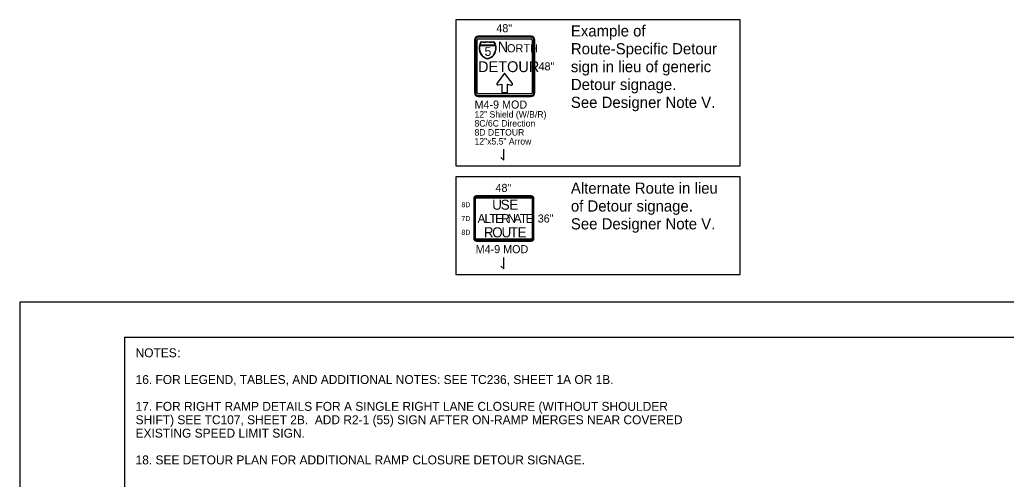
# Model space of a CAD drawing. Extents: x 99999 to 100116, y 99995 to 100013.
# Drawn here: x 100059.06 to 100067.9, y 100009.1 to 100013.22 of the extents above; entities that cross this region are included whole.
import ezdxf

# ---------------------------------------------------------------- set-up
doc = ezdxf.new("R2010")
doc.units = 0
for name, color, linetype in [('SH_GI_GeneralNotesBodyText', 7, 'Continuous'), ('SH_GI_PlotLimits', 7, 'Continuous'), ('SH_GI_SheetBorder', 7, 'Continuous'), ('TR_SN_ConstructionSigns', 7, 'Continuous'), ('TR_WZ_WorkZoneDetails', 7, 'Continuous')]:
    doc.layers.add(name, color=color, linetype=linetype)

msp = doc.modelspace()

# ---------------------------------------------------------------- linework, layer by layer
at = {"layer": 'SH_GI_PlotLimits'}
msp.add_lwpolyline([(100059.0625, 99999.6875), (100076.0625, 99999.6875), (100076.0625, 100010.6875), (100059.0625, 100010.6875)], close=True, dxfattribs=at)
at = {"layer": 'SH_GI_SheetBorder'}
for q in [(100060, 100000), (100075.75, 100010.375)]:
    msp.add_line((100060, 100010.375), q, dxfattribs=at)
at = {"layer": 'TR_SN_ConstructionSigns'}
for p, q in [((100063.1354, 100013.0373), (100063.1354, 100012.5648)), ((100063.1438, 100013.0373), (100063.1438, 100012.5648)), ((100063.1579, 100012.5648), (100063.1579, 100013.0373)), ((100063.6416, 100013.0711), (100063.1691, 100013.0711)), ((100063.6416, 100013.0626), (100063.1691, 100013.0626)), ((100063.1691, 100013.0486), (100063.6416, 100013.0486)), ((100063.6529, 100013.0373), (100063.6529, 100012.5648)), ((100063.6669, 100012.5648), (100063.6669, 100013.0373)), ((100063.6754, 100012.5648), (100063.6754, 100013.0373)), ((100063.3228, 100012.9875), (100063.1823, 100012.9875)), ((100063.1823, 100012.9875), (100063.3228, 100012.9875)), ((100063.1834, 100012.9912), (100063.3217, 100012.9912)), ((100063.3217, 100012.9912), (100063.1834, 100012.9912)), ((100063.6416, 100012.5536), (100063.1691, 100012.5536)), ((100063.1691, 100012.5395), (100063.6416, 100012.5395)), ((100063.1691, 100012.5311), (100063.6416, 100012.5311)), ((100063.6424, 100011.6405), (100063.153, 100011.6405)), ((100063.6424, 100011.6335), (100063.153, 100011.6335)), ((100063.153, 100011.6236), (100063.6424, 100011.6236)), ((100063.1277, 100011.6152), (100063.1277, 100011.2608)), ((100063.1347, 100011.6152), (100063.1347, 100011.2608)), ((100063.1446, 100011.2608), (100063.1446, 100011.6152)), ((100063.6508, 100011.6152), (100063.6508, 100011.2608)), ((100063.6607, 100011.2608), (100063.6607, 100011.6152)), ((100063.6677, 100011.2608), (100063.6677, 100011.6152)), ((100063.6424, 100011.2524), (100063.153, 100011.2524)), ((100063.153, 100011.2425), (100063.6424, 100011.2425)), ((100063.153, 100011.2355), (100063.6424, 100011.2355))]:
    msp.add_line(p, q, dxfattribs=at)
msp.add_lwpolyline([(100063.3367, 100012.6494), (100063.3356, 100012.6478), (100063.335, 100012.6461), (100063.3347, 100012.6441), (100063.3348, 100012.6424), (100063.335, 100012.6412), (100063.3356, 100012.6398), (100063.3373, 100012.6375), (100063.3386, 100012.6364), (100063.34, 100012.6355), (100063.3417, 100012.6348), (100063.3432, 100012.6345), (100063.3447, 100012.6343), (100063.3465, 100012.6343), (100063.3478, 100012.6346), (100063.3795, 100012.6424), (100063.3795, 100012.5671), (100063.4307, 100012.5671), (100063.4307, 100012.6429), (100063.4617, 100012.6337), (100063.4647, 100012.6331), (100063.4681, 100012.6334), (100063.4703, 100012.6342), (100063.4733, 100012.6362), (100063.4752, 100012.6389), (100063.476, 100012.6414), (100063.4761, 100012.6436), (100063.4754, 100012.6463), (100063.4746, 100012.6477), (100063.4051, 100012.7405), (100063.3367, 100012.6494)], dxfattribs=at)
for centre, radius, start, end in [((100063.1691, 100013.0373), 0.0337, 90, 180), ((100063.1691, 100013.0373), 0.0253, 90, 180), ((100063.1691, 100013.0373), 0.0113, 90, 180), ((100063.6416, 100013.0373), 0.0338, 360, 90), ((100063.6416, 100013.0373), 0.0253, 360, 90), ((100063.6416, 100013.0373), 0.0113, 360, 90), ((100063.2725, 100012.9642), 0.0973, 142.16169, 258.18105), ((100063.2715, 100012.9633), 0.0925, 164.85517, 258.18105), ((100063.2715, 100012.9633), 0.0925, 164.85517, 258.18105), ((100063.2715, 100012.9633), 0.0925, 142.16169, 162.48397), ((100063.2715, 100012.9633), 0.0925, 142.16169, 162.48397), ((100063.2245, 100013.1212), 0.1014, 253.48525, 286.04538), ((100063.2259, 100013.1124), 0.0964, 253.48525, 286.04538), ((100063.2259, 100013.1124), 0.0964, 253.48525, 286.04538), ((100063.2806, 100013.1212), 0.1014, 253.95462, 286.51475), ((100063.2792, 100013.1124), 0.0964, 253.95462, 286.51475), ((100063.2792, 100013.1124), 0.0964, 253.95462, 286.51475), ((100063.2325, 100012.9642), 0.0974, 281.90384, 37.84925), ((100063.2335, 100012.9633), 0.0925, 281.90384, 15.1558), ((100063.2335, 100012.9633), 0.0925, 281.90384, 15.1558), ((100063.2335, 100012.9633), 0.0925, 17.52691, 37.84925), ((100063.2335, 100012.9633), 0.0925, 17.52691, 37.84925), ((100063.1691, 100012.5648), 0.0338, 180, 270), ((100063.1691, 100012.5648), 0.0253, 180, 270), ((100063.1691, 100012.5648), 0.0113, 180, 270), ((100063.6416, 100012.5648), 0.0337, 270, 360), ((100063.6416, 100012.5648), 0.0253, 270, 0), ((100063.6416, 100012.5648), 0.0113, 270, 0), ((100063.153, 100011.6152), 0.0253, 90, 180), ((100063.153, 100011.6152), 0.0183, 90, 180), ((100063.153, 100011.6152), 0.00844, 90, 180), ((100063.6424, 100011.6152), 0.0253, 360, 90), ((100063.6424, 100011.6152), 0.0183, 360, 90), ((100063.6424, 100011.6152), 0.00844, 360, 90), ((100063.153, 100011.2608), 0.0253, 180, 270), ((100063.153, 100011.2608), 0.0183, 180, 270), ((100063.153, 100011.2608), 0.00844, 180, 270), ((100063.6424, 100011.2608), 0.0253, 270, 360), ((100063.6424, 100011.2608), 0.0183, 270, 0), ((100063.6424, 100011.2608), 0.00844, 270, 0)]:
    msp.add_arc(centre, radius, start, end, dxfattribs=at)
at = {"layer": 'TR_WZ_WorkZoneDetails'}
for p, q in [((100063.3963, 100011.9605), (100063.3963, 100012.0605)), ((100063.3713, 100011.9855), (100063.3963, 100011.9605)), ((100063.3963, 100010.9875), (100063.3963, 100011.0875)), ((100063.3713, 100011.0125), (100063.3963, 100010.9875))]:
    msp.add_line(p, q, dxfattribs=at)
for points in [[(100062.9666, 100011.9105), (100065.5143, 100011.9105), (100065.5143, 100013.2191), (100062.9666, 100013.2191)], [(100062.9666, 100010.9375), (100065.5143, 100010.9375), (100065.5143, 100011.8105), (100062.9666, 100011.8105)]]:
    msp.add_lwpolyline(points, close=True, dxfattribs=at)

# ---------------------------------------------------------------- texts
at = {"layer": 'SH_GI_GeneralNotesBodyText'}
for s, p in [('NOTES', (100060.1, 100010.195)), (':', (100060.4743, 100010.195)), ('16. FOR LEGEND, TABLES, AND ADDITIONAL NOTES: SEE TC236, SHEET 1A OR 1B.', (100060.1, 100009.955)), ('17. FOR RIGHT RAMP DETAILS FOR A SINGLE RIGHT LANE CLOSURE (WITHOUT SHOULDER ', (100060.1, 100009.715)), ('SHIFT) SEE TC107, SHEET 2B.  ADD R2-1 (55) SIGN AFTER ON-RAMP MERGES NEAR COVERED ', (100060.1, 100009.595)), ('EXISTING SPEED LIMIT SIGN.', (100060.1, 100009.475)), ('18. SEE DETOUR PLAN FOR ADDITIONAL RAMP CLOSURE DETOUR SIGNAGE.', (100060.1, 100009.235))]:
    msp.add_text(s, height=0.08, rotation=360, dxfattribs=at).set_placement(p)
at = {"layer": 'TR_SN_ConstructionSigns'}
for s, height, p in [('48"', 0.072, (100063.3306, 100013.1071)), ('5', 0.081, (100063.2253, 100012.8951)), ('N', 0.0972, (100063.3432, 100012.9267)), ('ORTH', 0.0729, (100063.4264, 100012.9267)), ('DETOUR', 0.0972, (100063.1668, 100012.7497)), ('48"', 0.072, (100063.7086, 100012.7651)), ('M4-9 MOD', 0.072, (100063.1354, 100012.4231)), ('12" Shield (W/B/R)', 0.0576, (100063.1354, 100012.3424)), ('8C/6C Direction', 0.0576, (100063.1354, 100012.2618)), ('8D DETOUR', 0.0576, (100063.1354, 100012.1811)), ('12"x5.5" Arrow', 0.0576, (100063.1354, 100012.1005)), ('48"', 0.072, (100063.323, 100011.6765)), ('36"', 0.072, (100063.7015, 100011.402)), ('M4-9 MOD', 0.072, (100063.1457, 100011.1275))]:
    msp.add_text(s, height=height, rotation=360, dxfattribs=at).set_placement(p)
for s, height, p in [('8D', 0.045, (100063.018, 100011.5392)), ('U', 0.09, (100063.2933, 100011.5167)), ('S', 0.09, (100063.3698, 100011.5167)), ('E', 0.09, (100063.4463, 100011.5167)), ('7D', 0.045, (100063.018, 100011.4155)), ('A', 0.0787, (100063.1626, 100011.3986)), ('L', 0.0787, (100063.2241, 100011.3986)), ('T', 0.0787, (100063.269, 100011.3986)), ('E', 0.0787, (100063.3201, 100011.3986)), ('R', 0.0787, (100063.3737, 100011.3986)), ('N', 0.0787, (100063.4312, 100011.3986)), ('A', 0.0787, (100063.4863, 100011.3986)), ('T', 0.0787, (100063.5414, 100011.3986)), ('E', 0.0787, (100063.5926, 100011.3986)), ('R', 0.09, (100063.2186, 100011.2692)), ('O', 0.09, (100063.2933, 100011.2692)), ('U', 0.09, (100063.377, 100011.2692)), ('T', 0.09, (100063.4517, 100011.2692)), ('E', 0.09, (100063.521, 100011.2692)), ('8D', 0.045, (100063.018, 100011.2917))]:
    msp.add_text(s, height=height, dxfattribs=at).set_placement(p)
at = {"layer": 'TR_WZ_WorkZoneDetails'}
for s, p in [('Example of ', (100063.9983, 100013.0691)), ('Route-Specific Detour ', (100063.9983, 100012.9091)), ('sign in lieu of generic ', (100063.9983, 100012.7491)), ('Detour signage.', (100063.9983, 100012.5891)), ('See Designer Note V.', (100063.9983, 100012.4291)), ('Alternate Route in lieu ', (100063.9983, 100011.6605)), ('of Detour signage.', (100063.9983, 100011.5005)), ('See Designer Note V.', (100063.9983, 100011.3405))]:
    msp.add_text(s, height=0.1, dxfattribs=at).set_placement(p)

doc.saveas('drawing.dxf')
